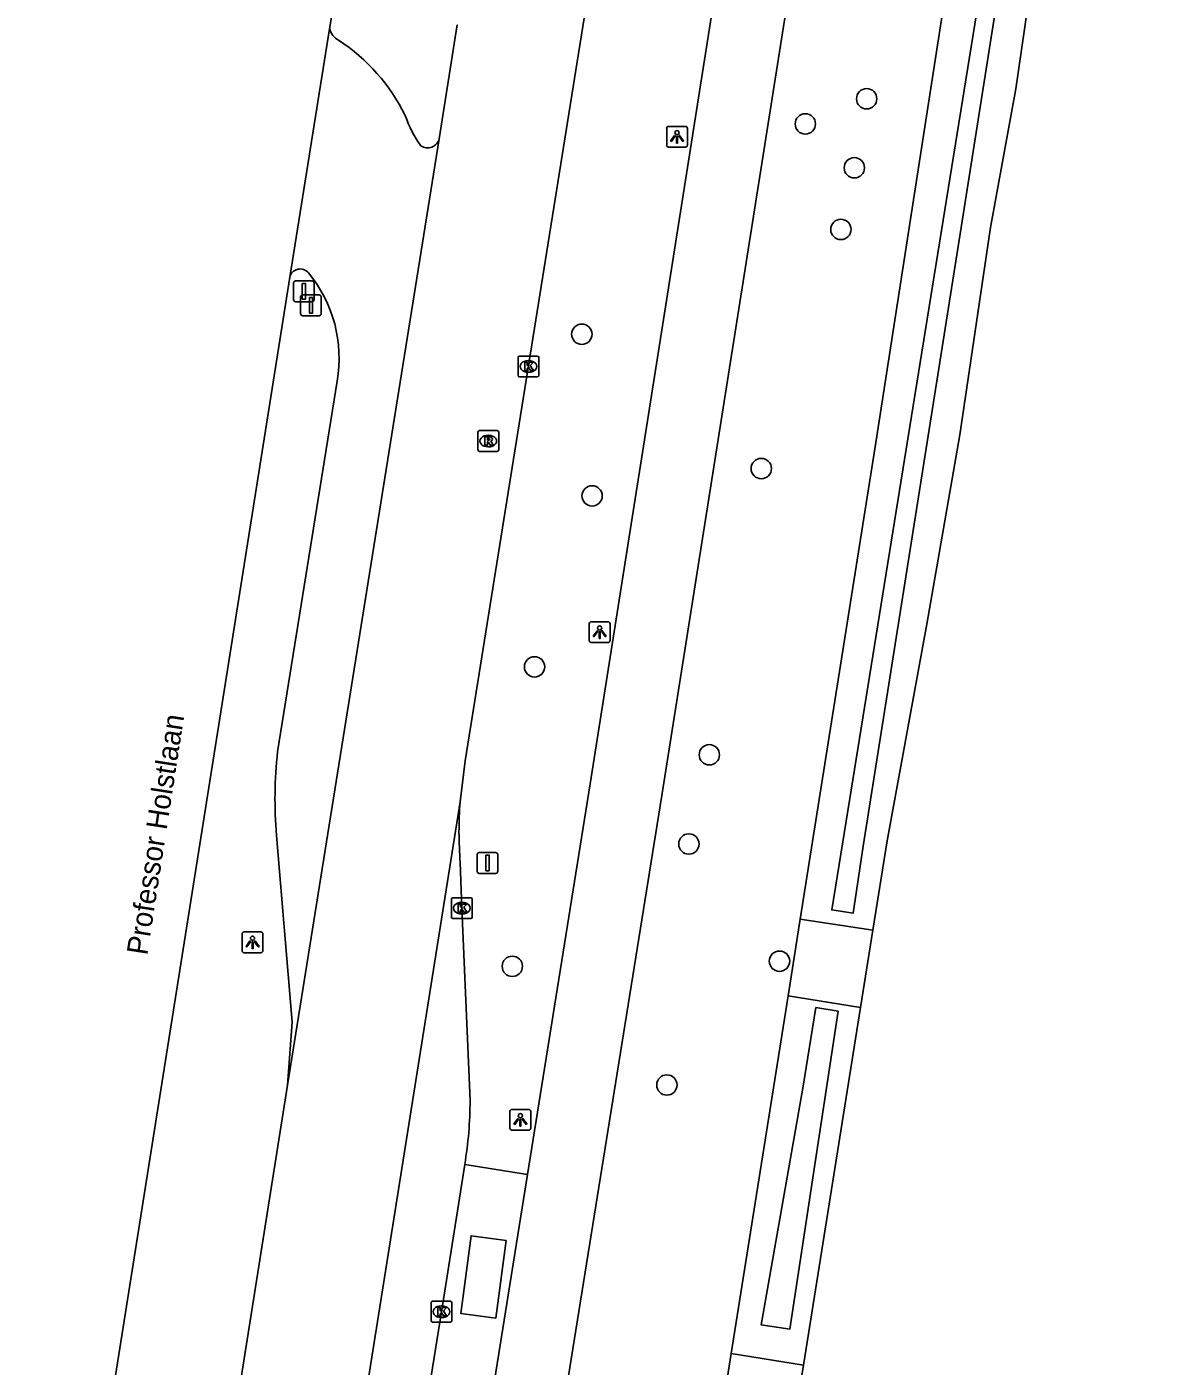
# Model space of a CAD drawing. Extents: x 160203 to 161526, y 379529 to 381797.
# Drawn here: x 160315.5 to 160369.8, y 380364.3 to 380428.7 of the extents above; entities that cross this region are included whole.
import ezdxf

# ---------------------------------------------------------------- set-up
doc = ezdxf.new("R2010")
doc.units = 0
for name, color, linetype in [('IMGEO_Berm_groen', 7, 'Continuous'), ('IMGEO_Boom', 7, 'Continuous'), ('IMGEO_Fietspad_gesloten', 7, 'Continuous'), ('IMGEO_Grasland_agrarisch', 7, 'Continuous'), ('IMGEO_Groenvoorziening', 7, 'Continuous'), ('IMGEO_Kolk', 7, 'Continuous'), ('IMGEO_Lichtpunt', 7, 'Continuous'), ('IMGEO_Openbare_ruimte_label', 7, 'Continuous'), ('IMGEO_OVBaan_gesloten', 7, 'Continuous'), ('IMGEO_Rijbaan_regionaal_gesloten', 7, 'Continuous'), ('IMGEO_Rioolput', 7, 'Continuous'), ('IMGEO_Verkeersbordpaal', 7, 'Continuous'), ('IMGEO_Voetpad_gesloten', 7, 'Continuous'), ('IMGEO_Voetpad_open', 7, 'Continuous'), ('IMGEO_Waterloop', 7, 'Continuous')]:
    doc.layers.add(name, color=color, linetype=linetype)

msp = doc.modelspace()

# ---------------------------------------------------------------- linework, layer by layer
at = {"layer": 'IMGEO_Berm_groen'}
for points in [[(160352.684, 380385.815), (160356.287, 380408.516), (160361.612, 380442.808), (160363.62, 380454.848), (160364.253, 380457.684), (160365.385, 380465.491), (160366.679, 380472.607), (160367.782, 380480.751), (160370.802, 380500), (160371.249, 380502.852), (160372.818, 380512.852), (160374.702, 380524.857), (160374.72, 380524.951), (160376.133, 380532.248), (160378.196, 380546.027), (160380.328, 380558.075), (160380.897, 380562.583), (160383.168, 380574.421), (160385.043, 380587.001), (160386.211, 380592.747), (160387.862, 380603.942)], [(160352.1, 380382.133), (160352.684, 380385.815)], [(160349.372, 380364.94), (160352.1, 380382.133)], [(160348.502, 380359.458), (160349.372, 380364.94)]]:
    msp.add_lwpolyline(points, dxfattribs=at)
at = {"layer": 'IMGEO_Boom'}
for centre in [(160355.88, 380425.256), (160352.932, 380424.044), (160355.286, 380421.937), (160354.643, 380418.975), (160342.192, 380413.936), (160350.816, 380407.479), (160342.686, 380406.167), (160339.919, 380397.949), (160348.319, 380393.722), (160347.336, 380389.435), (160338.851, 380383.555), (160351.691, 380383.802), (160346.279, 380377.851)]:
    msp.add_circle(centre, 0.489, dxfattribs=at)
at = {"layer": 'IMGEO_Fietspad_gesloten'}
for points in [[(160339.578, 380373.55), (160342.587, 380392.328), (160351.85, 380450.983)], [(160355.339, 380450.611), (160346.029, 380391.769), (160338.96, 380347.733), (160332.907, 380309.531)], [(160339.578, 380373.55), (160329.428, 380310.134)]]:
    msp.add_lwpolyline(points, dxfattribs=at)
at = {"layer": 'IMGEO_Grasland_agrarisch'}
for points in [[(160391.591, 380603.409), (160387.523, 380579.574), (160379.296, 380526.737), (160378.851, 380524.294), (160377.634, 380517.623), (160376.818, 380512.224), (160375.308, 380502.238), (160374.97, 380500), (160372.848, 380488.626), (160370.146, 380472.104), (160369.369, 380465.742), (160366.989, 380450.176), (160364.586, 380436.343), (160363.043, 380425.732), (160361.825, 380419.072), (160360.362, 380409.1), (160358.765, 380400.008), (160356.87, 380389.591), (160356.183, 380385.289)], [(160355.589, 380381.575), (160356.183, 380385.289)], [(160355.589, 380381.575), (160352.843, 380364.39)], [(160351.967, 380358.904), (160352.843, 380364.39)]]:
    msp.add_lwpolyline(points, dxfattribs=at)
at = {"layer": 'IMGEO_Groenvoorziening'}
for points in [[(160356.183, 380385.289), (160352.684, 380385.815)], [(160352.1, 380382.133), (160355.589, 380381.575)], [(160352.843, 380364.39), (160349.372, 380364.94)]]:
    msp.add_lwpolyline(points, dxfattribs=at)
at = {"layer": 'IMGEO_Kolk'}
for p, q in [((160339.2, 380412.888), (160340.052, 380412.888)), ((160339.125, 380411.962), (160339.125, 380412.814)), ((160339.613, 380412.668), (160339.638, 380412.668)), ((160340.126, 380412.814), (160340.126, 380411.962)), ((160340.052, 380411.888), (160339.2, 380411.888)), ((160339.636, 380412.108), (160339.611, 380412.108)), ((160335.923, 380385.924), (160335.923, 380386.776)), ((160335.998, 380386.85), (160336.85, 380386.85)), ((160336.411, 380386.63), (160336.436, 380386.63)), ((160336.924, 380386.776), (160336.924, 380385.924)), ((160336.85, 380385.85), (160335.998, 380385.85)), ((160336.434, 380386.07), (160336.409, 380386.07)), ((160334.946, 380366.527), (160334.946, 380367.379)), ((160335.021, 380367.453), (160335.873, 380367.453)), ((160335.434, 380367.233), (160335.459, 380367.233)), ((160335.947, 380367.379), (160335.947, 380366.527)), ((160335.457, 380366.673), (160335.432, 380366.673)), ((160335.873, 380366.453), (160335.021, 380366.453))]:
    msp.add_line(p, q, dxfattribs=at)
for points in [[(160339.2, 380412.888), (160340.052, 380412.888)], [(160339.125, 380411.962), (160339.125, 380412.814)], [(160339.446, 380412.588), (160339.569, 380412.588), (160339.569, 380412.437), (160339.699, 380412.588), (160339.863, 380412.588), (160339.717, 380412.437), (160339.87, 380412.188), (160339.718, 380412.188), (160339.633, 380412.352), (160339.569, 380412.285), (160339.569, 380412.188), (160339.446, 380412.188), (160339.446, 380412.588)], [(160340.126, 380412.814), (160340.126, 380411.962)], [(160340.052, 380411.888), (160339.2, 380411.888)], [(160335.923, 380385.924), (160335.923, 380386.776)], [(160335.998, 380386.85), (160336.85, 380386.85)], [(160336.244, 380386.55), (160336.367, 380386.55), (160336.367, 380386.399), (160336.497, 380386.55), (160336.661, 380386.55), (160336.515, 380386.399), (160336.668, 380386.15), (160336.516, 380386.15), (160336.431, 380386.314), (160336.367, 380386.247), (160336.367, 380386.15), (160336.244, 380386.15), (160336.244, 380386.55)], [(160336.924, 380386.776), (160336.924, 380385.924)], [(160336.85, 380385.85), (160335.998, 380385.85)], [(160334.946, 380366.527), (160334.946, 380367.379)], [(160335.021, 380367.453), (160335.873, 380367.453)], [(160335.267, 380367.153), (160335.39, 380367.153), (160335.39, 380367.002), (160335.52, 380367.153), (160335.684, 380367.153), (160335.538, 380367.002), (160335.691, 380366.753), (160335.539, 380366.753), (160335.454, 380366.917), (160335.39, 380366.85), (160335.39, 380366.753), (160335.267, 380366.753), (160335.267, 380367.153)], [(160335.947, 380367.379), (160335.947, 380366.527)], [(160335.873, 380366.453), (160335.021, 380366.453)]]:
    msp.add_lwpolyline(points, dxfattribs=at)
for centre, start, end in [((160339.202, 380412.812), 91.55205, 178.44795), ((160339.202, 380412.812), 91.55205, 178.44795), ((160340.05, 380412.812), 1.55205, 88.44795), ((160340.05, 380412.812), 1.55205, 88.44795), ((160339.202, 380411.964), 181.55205, 268.44795), ((160339.202, 380411.964), 181.55205, 268.44795), ((160340.05, 380411.964), 271.55205, 358.44795), ((160340.05, 380411.964), 271.55205, 358.44795), ((160336, 380386.774), 91.55205, 178.44795), ((160336, 380386.774), 91.55205, 178.44795), ((160336.848, 380386.774), 1.55205, 88.44795), ((160336.848, 380386.774), 1.55205, 88.44795), ((160336, 380385.926), 181.55205, 268.44795), ((160336, 380385.926), 181.55205, 268.44795), ((160336.848, 380385.926), 271.55205, 358.44795), ((160336.848, 380385.926), 271.55205, 358.44795), ((160335.023, 380367.377), 91.55205, 178.44795), ((160335.023, 380367.377), 91.55205, 178.44795), ((160335.871, 380367.377), 1.55205, 88.44795), ((160335.871, 380367.377), 1.55205, 88.44795), ((160335.023, 380366.529), 181.55205, 268.44795), ((160335.023, 380366.529), 181.55205, 268.44795), ((160335.871, 380366.529), 271.55205, 358.44795), ((160335.871, 380366.529), 271.55205, 358.44795)]:
    msp.add_arc(centre, 0.0765, start, end, dxfattribs=at)
for centre, major_axis, ratio, start_param, end_param in [((160339.612, 380412.388), (-0.387, 0.002), 0.722429, 4.712389, 7.853982), ((160339.637, 380412.388), (-0.39, 0.002), 0.717154, 1.570796, 4.712389), ((160336.41, 380386.35), (-0.387, 0.002), 0.722429, 4.712389, 7.853982), ((160336.435, 380386.35), (-0.39, 0.002), 0.717154, 1.570796, 4.712389), ((160335.433, 380366.953), (-0.387, 0.002), 0.722429, 4.712389, 7.853982), ((160335.458, 380366.953), (-0.39, 0.002), 0.717154, 1.570796, 4.712389)]:
    msp.add_ellipse(centre, major_axis=major_axis, ratio=ratio, start_param=start_param, end_param=end_param, dxfattribs=at)
at = {"layer": 'IMGEO_Lichtpunt'}
for p, q in [((160346.269, 380423.83), (160346.269, 380423.023)), ((160346.269, 380423.83), (160346.269, 380423.023)), ((160347.171, 380423.925), (160346.363, 380423.925)), ((160347.171, 380423.925), (160346.363, 380423.925)), ((160347.265, 380423.023), (160347.265, 380423.83)), ((160347.265, 380423.023), (160347.265, 380423.83)), ((160346.363, 380422.929), (160347.171, 380422.929)), ((160346.363, 380422.929), (160347.171, 380422.929)), ((160342.55, 380400.02), (160342.55, 380399.213)), ((160342.55, 380400.02), (160342.55, 380399.213)), ((160343.452, 380400.115), (160342.644, 380400.115)), ((160343.452, 380400.115), (160342.644, 380400.115)), ((160343.546, 380399.213), (160343.546, 380400.02)), ((160343.546, 380399.213), (160343.546, 380400.02)), ((160342.644, 380399.119), (160343.452, 380399.119)), ((160342.644, 380399.119), (160343.452, 380399.119)), ((160326.77, 380385.206), (160325.962, 380385.206)), ((160326.77, 380385.206), (160325.962, 380385.206)), ((160325.868, 380385.111), (160325.868, 380384.304)), ((160325.868, 380385.111), (160325.868, 380384.304)), ((160326.864, 380384.304), (160326.864, 380385.111)), ((160326.864, 380384.304), (160326.864, 380385.111)), ((160325.962, 380384.21), (160326.77, 380384.21)), ((160325.962, 380384.21), (160326.77, 380384.21)), ((160338.74, 380376.58), (160338.74, 380375.773)), ((160338.74, 380376.58), (160338.74, 380375.773)), ((160339.642, 380376.675), (160338.834, 380376.675)), ((160339.642, 380376.675), (160338.834, 380376.675)), ((160339.736, 380375.773), (160339.736, 380376.58)), ((160339.736, 380375.773), (160339.736, 380376.58)), ((160338.834, 380375.679), (160339.642, 380375.679)), ((160338.834, 380375.679), (160339.642, 380375.679))]:
    msp.add_line(p, q, dxfattribs=at)
for points in [[(160346.643, 380423.494), (160346.682, 380423.466), (160346.494, 380423.204), (160346.456, 380423.231), (160346.643, 380423.494)], [(160346.745, 380423.446), (160346.792, 380423.446), (160346.792, 380423.124), (160346.745, 380423.124), (160346.745, 380423.446)], [(160346.855, 380423.466), (160346.893, 380423.493), (160347.08, 380423.231), (160347.041, 380423.203), (160346.855, 380423.466)], [(160342.924, 380399.684), (160342.963, 380399.656), (160342.775, 380399.394), (160342.737, 380399.421), (160342.924, 380399.684)], [(160343.026, 380399.636), (160343.073, 380399.636), (160343.073, 380399.314), (160343.026, 380399.314), (160343.026, 380399.636)], [(160343.136, 380399.656), (160343.174, 380399.683), (160343.361, 380399.421), (160343.322, 380399.393), (160343.136, 380399.656)], [(160326.242, 380384.775), (160326.281, 380384.747), (160326.093, 380384.485), (160326.055, 380384.512), (160326.242, 380384.775)], [(160326.344, 380384.727), (160326.391, 380384.727), (160326.391, 380384.405), (160326.344, 380384.405), (160326.344, 380384.727)], [(160326.454, 380384.747), (160326.492, 380384.774), (160326.679, 380384.512), (160326.64, 380384.484), (160326.454, 380384.747)], [(160339.114, 380376.244), (160339.153, 380376.216), (160338.965, 380375.954), (160338.927, 380375.981), (160339.114, 380376.244)], [(160339.216, 380376.196), (160339.263, 380376.196), (160339.263, 380375.874), (160339.216, 380375.874), (160339.216, 380376.196)], [(160339.326, 380376.216), (160339.364, 380376.243), (160339.551, 380375.981), (160339.512, 380375.953), (160339.326, 380376.216)]]:
    msp.add_lwpolyline(points, dxfattribs=at)
for centre in [(160346.768, 380423.628), (160343.049, 380399.818), (160326.367, 380384.909), (160339.239, 380376.378)]:
    msp.add_circle(centre, 0.0994, dxfattribs=at)
for centre, start, end in [((160346.363, 380423.83), 90, 180), ((160346.363, 380423.83), 90, 180), ((160347.171, 380423.83), 0, 90), ((160347.171, 380423.83), 0, 90), ((160346.363, 380423.023), 180, 270), ((160346.363, 380423.023), 180, 270), ((160347.171, 380423.023), 270, 0), ((160347.171, 380423.023), 270, 360), ((160342.644, 380400.02), 90, 180), ((160342.644, 380400.02), 90, 180), ((160343.452, 380400.02), 0, 90), ((160343.452, 380400.02), 0, 90), ((160342.644, 380399.213), 180, 270), ((160342.644, 380399.213), 180, 270), ((160343.452, 380399.213), 270, 0), ((160343.452, 380399.213), 270, 360), ((160325.962, 380385.111), 90, 180), ((160325.962, 380385.111), 90, 180), ((160326.77, 380385.111), 0, 90), ((160326.77, 380385.111), 0, 90), ((160325.962, 380384.304), 180, 270), ((160325.962, 380384.304), 180, 270), ((160326.77, 380384.304), 270, 0), ((160326.77, 380384.304), 270, 360), ((160338.834, 380376.58), 90, 180), ((160338.834, 380376.58), 90, 180), ((160339.642, 380376.58), 0, 90), ((160339.642, 380376.58), 0, 90), ((160338.834, 380375.773), 180, 270), ((160338.834, 380375.773), 180, 270), ((160339.642, 380375.773), 270, 0), ((160339.642, 380375.773), 270, 360)]:
    msp.add_arc(centre, 0.0946, start, end, dxfattribs=at)
at = {"layer": 'IMGEO_OVBaan_gesloten'}
for points in [[(160324.382, 380316.217), (160336.341, 380391.468)], [(160336.351, 380388.549), (160336.423, 380386.35), (160336.819, 380377.111)], [(160327.151, 380326.513), (160330.821, 380339.612), (160331.689, 380343.518), (160332.509, 380348.694), (160335.445, 380366.954), (160336.565, 380374.023)]]:
    msp.add_lwpolyline(points, dxfattribs=at)
for centre, radius, start, end in [((160355.003, 380390.072), 18.714, 175.72316, 184.66941), ((160318.093, 380377.097), 18.726, 350.55219, 0.04338)]:
    msp.add_arc(centre, radius, start, end, dxfattribs=at)
at = {"layer": 'IMGEO_Rijbaan_regionaal_gesloten'}
for points in [[(160336.341, 380391.468), (160336.593, 380393.432), (160342.705, 380431.641), (160345.925, 380451.876), (160349.015, 380471.121), (160352.416, 380492.353), (160353.625, 380500), (160355.297, 380510.581), (160358.035, 380527.602), (160358.549, 380530.801), (160361.773, 380551.056), (160364.666, 380569.299), (160367.388, 380586.261)], [(160330.069, 380428.623), (160330.26, 380429.737)], [(160328.155, 380416.671), (160330.069, 380428.623)], [(160336.207, 380428.804), (160335.344, 380423.335)], [(160335.344, 380423.335), (160328.049, 380377.845)], [(160315.52, 380337.005), (160317.914, 380352.077), (160328.155, 380416.671)], [(160330.43, 380411.684), (160327.57, 380393.867)], [(160327.524, 380389.85), (160328.276, 380380.878), (160328.049, 380377.845)], [(160328.049, 380377.845), (160323.805, 380351.043), (160319.87, 380326.164)]]:
    msp.add_lwpolyline(points, dxfattribs=at)
for centre, radius, start, end in [((160330.858, 380428.799), 0.808, 192.55563, 244.17934), ((160325.457, 380420.391), 9.191, 26.21997, 56.67657), ((160339.866, 380426.673), 6.552, 199.81689, 214.24736), ((160334.77, 380423.486), 0.593, 237.36419, 345.2852), ((160328.657, 380416.559), 0.514, 39.50206, 167.39779), ((160324.114, 380412.796), 6.414, 350.01373, 39.61864), ((160347.871, 380391.626), 20.424, 173.69997, 184.98786)]:
    msp.add_arc(centre, radius, start, end, dxfattribs=at)
at = {"layer": 'IMGEO_Rioolput'}
for p, q in [((160337.196, 380408.376), (160337.196, 380409.228)), ((160337.271, 380409.302), (160338.123, 380409.302)), ((160337.684, 380409.082), (160337.709, 380409.082)), ((160338.197, 380409.228), (160338.197, 380408.376)), ((160337.707, 380408.522), (160337.682, 380408.522)), ((160338.123, 380408.302), (160337.271, 380408.302))]:
    msp.add_line(p, q, dxfattribs=at)
for points in [[(160337.196, 380408.376), (160337.196, 380409.228)], [(160337.271, 380409.302), (160338.123, 380409.302)], [(160337.785, 380409), (160337.533, 380409.002), (160337.533, 380408.602)], [(160338.197, 380409.228), (160338.197, 380408.376)], [(160337.533, 380408.602), (160337.657, 380408.602), (160337.657, 380408.764), (160337.668, 380408.764)], [(160337.711, 380408.921), (160337.657, 380408.921), (160337.657, 380408.84)], [(160337.657, 380408.84), (160337.709, 380408.84)], [(160337.715, 380408.735), (160337.786, 380408.602), (160337.926, 380408.602), (160337.861, 380408.728)], [(160338.123, 380408.302), (160337.271, 380408.302)]]:
    msp.add_lwpolyline(points, dxfattribs=at)
for centre, radius, start, end in [((160337.273, 380409.226), 0.0765, 91.55205, 178.44795), ((160337.273, 380409.226), 0.0765, 91.55205, 178.44795), ((160337.784, 380408.89), 0.109, 350.36119, 89.41601), ((160338.121, 380409.226), 0.0765, 1.55205, 88.44795), ((160338.121, 380409.226), 0.0765, 1.55205, 88.44795), ((160337.273, 380408.378), 0.0765, 181.55205, 268.44795), ((160337.273, 380408.378), 0.0765, 181.55205, 268.44795), ((160337.667, 380408.711), 0.0533, 26.02933, 88.69889), ((160337.693, 380409.029), 0.19, 274.7715, 282.96867), ((160337.717, 380408.825), 0.0964, 77.00612, 93.18647), ((160337.731, 380408.882), 0.0378, 276.66336, 79.67722), ((160337.782, 380408.89), 0.112, 277.58423, 350.98172), ((160337.766, 380408.675), 0.108, 29.51342, 73.79051), ((160338.121, 380408.378), 0.0765, 271.55205, 358.44795), ((160338.121, 380408.378), 0.0765, 271.55205, 358.44795)]:
    msp.add_arc(centre, radius, start, end, dxfattribs=at)
for centre, major_axis, ratio, start_param, end_param in [((160337.683, 380408.802), (-0.387, 0.002), 0.722429, 4.712389, 7.853982), ((160337.708, 380408.802), (-0.39, 0.002), 0.717154, 1.570796, 4.712389)]:
    msp.add_ellipse(centre, major_axis=major_axis, ratio=ratio, start_param=start_param, end_param=end_param, dxfattribs=at)
at = {"layer": 'IMGEO_Verkeersbordpaal'}
for p, q in [((160328.337, 380415.6), (160328.337, 380416.4)), ((160328.337, 380416.4), (160328.337, 380415.6)), ((160328.437, 380416.5), (160329.227, 380416.5)), ((160329.227, 380416.5), (160328.437, 380416.5)), ((160329.327, 380416.4), (160329.327, 380415.6)), ((160329.327, 380415.6), (160329.327, 380416.4)), ((160329.227, 380415.5), (160328.437, 380415.5)), ((160328.437, 380415.5), (160329.227, 380415.5)), ((160328.68, 380414.926), (160328.68, 380415.726)), ((160328.68, 380415.726), (160328.68, 380414.926)), ((160328.78, 380415.826), (160329.57, 380415.826)), ((160329.57, 380415.826), (160328.78, 380415.826)), ((160329.67, 380415.726), (160329.67, 380414.926)), ((160329.67, 380414.926), (160329.67, 380415.726)), ((160329.57, 380414.826), (160328.78, 380414.826)), ((160328.78, 380414.826), (160329.57, 380414.826)), ((160337.261, 380389.023), (160338.051, 380389.023)), ((160338.051, 380389.023), (160337.261, 380389.023)), ((160337.161, 380388.123), (160337.161, 380388.923)), ((160337.161, 380388.923), (160337.161, 380388.123)), ((160338.151, 380388.923), (160338.151, 380388.123)), ((160338.151, 380388.123), (160338.151, 380388.923)), ((160338.051, 380388.023), (160337.261, 380388.023)), ((160337.261, 380388.023), (160338.051, 380388.023))]:
    msp.add_line(p, q, dxfattribs=at)
for points in [[(160328.757, 380416.375), (160328.907, 380416.375), (160328.907, 380415.625), (160328.757, 380415.625), (160328.757, 380416.375)], [(160329.1, 380415.701), (160329.25, 380415.701), (160329.25, 380414.951), (160329.1, 380414.951), (160329.1, 380415.701)], [(160337.581, 380388.898), (160337.731, 380388.898), (160337.731, 380388.148), (160337.581, 380388.148), (160337.581, 380388.898)]]:
    msp.add_lwpolyline(points, dxfattribs=at)
for centre, start, end in [((160328.437, 380416.4), 90, 180), ((160328.437, 380416.4), 90, 180), ((160329.227, 380416.4), 0, 90), ((160329.227, 380416.4), 360, 90), ((160328.437, 380415.6), 180, 270), ((160328.437, 380415.6), 180, 270), ((160328.78, 380415.726), 90, 180), ((160328.78, 380415.726), 90, 180), ((160329.227, 380415.6), 270, 0), ((160329.227, 380415.6), 270, 0), ((160329.57, 380415.726), 0, 90), ((160329.57, 380415.726), 360, 90), ((160328.78, 380414.926), 180, 270), ((160328.78, 380414.926), 180, 270), ((160329.57, 380414.926), 270, 0), ((160329.57, 380414.926), 270, 0), ((160337.261, 380388.923), 90, 180), ((160337.261, 380388.923), 90, 180), ((160338.051, 380388.923), 0, 90), ((160338.051, 380388.923), 360, 90), ((160337.261, 380388.123), 180, 270), ((160337.261, 380388.123), 180, 270), ((160338.051, 380388.123), 270, 0), ((160338.051, 380388.123), 270, 0)]:
    msp.add_arc(centre, 0.1, start, end, dxfattribs=at)
at = {"layer": 'IMGEO_Voetpad_gesloten'}
msp.add_lwpolyline([(160338.555, 380370.381), (160336.87, 380370.606), (160336.373, 380366.873), (160338.058, 380366.649), (160338.555, 380370.381)], dxfattribs=at)
at = {"layer": 'IMGEO_Voetpad_open'}
msp.add_lwpolyline([(160336.565, 380374.023), (160339.578, 380373.55)], dxfattribs=at)
at = {"layer": 'IMGEO_Waterloop'}
for points in [[(160390.283, 380602.648), (160386, 380577.395), (160377.268, 380524.546), (160375.458, 380513.613), (160373.434, 380501.388), (160370.437, 380483.285), (160366.048, 380454.705), (160360.368, 380418.754), (160355.719, 380389.323), (160355.227, 380386.102), (160354.2, 380386.268), (160354.809, 380390.039), (160357.778, 380408.419), (160361.753, 380433.029), (160367.445, 380469.514), (160370.699, 380490.376), (160372.531, 380501.536), (160374.537, 380513.764), (160376.097, 380523.266)], [(160354.51, 380381.398), (160353.441, 380381.571), (160352.815, 380377.697), (160350.809, 380366.324), (160352.18, 380366.115), (160354.51, 380381.398)]]:
    msp.add_lwpolyline(points, dxfattribs=at)

# ---------------------------------------------------------------- texts
at = {"layer": 'IMGEO_Openbare_ruimte_label'}
msp.add_text('Professor Holstlaan', height=1, rotation=81.1972, dxfattribs=at).set_placement((160321.303, 380384.057))

doc.saveas('drawing.dxf')
